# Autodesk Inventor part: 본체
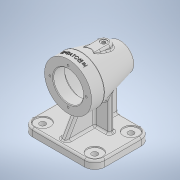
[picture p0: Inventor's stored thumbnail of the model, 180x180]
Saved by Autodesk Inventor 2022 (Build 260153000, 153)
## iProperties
Created: 2024-12
Part Number: 본체
Material: 일반
Document SubType Name: Modeling
Designer: PC-12
Density: 1 g/cm^3
Appearance: 기본값
Author: PC-12
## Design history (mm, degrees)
sketch "스케치1"
  geometry: L1 (0, -42)-(37, -42); L2 (37, -42)-(37, -22); L3 (37, -22)-(0, -22); L4 (0, -22)-(0, -42); L5 (37, -22)-(21, 42); L6 (21, 42)-(0, 42); L7 (0, 42)-(0, -22); L8 (-7.4, 0)-(44.4, 0) reference; 1 further point
  constraints: 14 end point, 2 horizontal, 2 parallel, 1 perpendicular, 1 point on line, 1 vertical, 1 other
  dimensions: "d0" = 74 diameter of L2 L4; "d1" = 84 distance between parallel lines of L6 L1; "d2" = 20 distance of L1.end L2.end; "d3" = 42 diameter of L5.end L7
revolve "회전1" sketch "스케치1" stored, may be unused: angle "d4" = 90 deg
node "작업 평면1"
sketch "스케치2"
  geometry: L1 (-57, 32)-(57, 32); L2 (57, 32)-(57, -57); L3 (57, -57)-(-57, -57); L4 (-57, -57)-(-57, 32); L5 (-21, 42)-(21, 42) reference; L6 (-37, -42)-(37, -42) reference; L7 (0, -90.26)-(0, 64.043) reference; 1 further point
  constraints: 8 end point, 2 parallel, 1 horizontal, 1 perpendicular, 1 other
  dimensions: "d6" = 89 distance of L3.end L1.start; "d7" = 114 distance of L2.end L3.end; "d8" = 15 distance between parallel lines of L6 L3
extrude "돌출1" join sketch "스케치2" distance "d9" = 12; taper "d10" = 0 deg
sketch "스케치3"
  geometry: L1 (28, -3)-(-28, -3); L2 (-28, -3)-(-28, 5); L3 (-28, 5)-(28, 5); L4 (28, 5)-(28, -3); L5 (28, -3)-(-28, 5); L6 (-28, -3)-(28, 5); L7 (-57, -32)-(57, -32) reference; L8 (0, 76.8)-(0, -61.8) reference; L9 (5, -32)-(-5, -32); L10 (-5, -32)-(-5, -3); L11 (-5, -3)-(5, -3); L12 (5, -3)-(5, -32); 5 further points
  constraints: 20 end point, 4 parallel, 3 midpoint, 3 point on line, 2 horizontal, 2 perpendicular, 1 other
  dimensions: "d11" = 29 distance between parallel lines of L7 L1; "d12" = 8 distance of L1.end L2.end; "d13" = 56 distance of L2.end L3.end; "d14" = 10 distance between parallel lines of L12 L10
extrude "돌출2" join sketch "스케치3" stored distance "d15" = 12; taper "d16" = 0 deg
sketch "스케치4"
  geometry: L1 (-70, 32)-(-70, -57) reference; L2 (-70, -50)-(0, -9.585); L3 (0, -76.8)-(0, 61.8) reference; L4 (-82, -57)-(-70, -57) reference; 1 further point
  constraints: 2 end point, 2 point on line
  dimensions: "d17" = 7 distance from line of L2.start L4; "d18" = 60 deg angle of L2 L1
feature "리브1" sketch "스케치4" dims "d19" = 1, "d20" = 10, "d21" = 0, "d22" = 0, "d23" = 1, "d24" = 1
sketch "스케치5" dims "d25" = 20
  geometry: L1 (-10, 14)-(10, 14); L2 (10, 14)-(10, -42); L3 (10, -42)-(-10, -42); L4 (-10, -42)-(-10, 14); L5 (-37, -42)-(37, -42) reference; L6 (0, 0)-(0, 14); 1 further point
  constraints: 10 end point, 3 vertical, 2 parallel, 1 collinear, 1 horizontal, 1 perpendicular, 3 other
  dimensions: "d26" = 56 distance between parallel lines of L1 L5
extrude "돌출3" join sketch "스케치5" distance "d27" = 33; taper "d28" = 0 deg
fillet "모깎기1" dims "d29" = 16
sketch "스케치6"
  geometry: A1 r 16 centre (41, 41) between (57, 41) and (41, 57) reference; A2 r 16 centre (41, -16) between (41, -32) and (57, -16) reference; A3 r 16 centre (-41, -16) between (-57, -16) and (-41, -32) reference; A4 r 16 centre (-41, 41) between (-41, 57) and (-57, 41) reference; 5 further points
  constraints: 4 coincident
hole "구멍1" sketch "스케치6" at (41, 41), (41, -16), (-41, -16), (-41, 41) diameter "d30" = 9; stored, may be unused: countersink angle "d34" = 90 deg, drill point angle "d36" = 118 deg; dims "d31" = 8, "d32" = 24, "d33" = 2, "d35" = 10
sketch "스케치7"
  geometry: L1 (-37, -42)-(37, -42) reference; L2 (23.5, -42)-(0, -42); L3 (0, -42)-(0, -24); L4 (0, -24)-(23.5, -24); L5 (23.5, -24)-(23.5, -42); L6 (-21, 42)-(21, 42) reference; L7 (0, -24)-(0, 21); L8 (23.5, -24)-(32.346, -24); L9 (32.346, -24)-(21.096, 21); L10 (21, 42)-(37, -22) reference; L11 (0, 21)-(17.5, 21); L12 (17.5, 21)-(17.5, 31); L13 (17.5, 31)-(0, 31); L14 (0, 31)-(0, 21); L15 (21.096, 21)-(17.5, 21); L16 (0, 31)-(15.5, 31); L17 (15.5, 31)-(15.5, 34); L18 (15.5, 34)-(0, 34); L19 (0, 34)-(0, 31); 2 further points
  constraints: 32 end point, 7 parallel, 5 horizontal, 3 perpendicular, 2 point on line, 1 vertical
  dimensions: "d37" = 18 distance of L4.end L2.start; "d38" = 47 diameter of L5 L3; "d41" = 5 distance between parallel lines of L10 L9; "d42" = 45 distance between parallel lines of L11 L4; "d43" = 35 diameter of L12 L14; "d44" = 31 diameter of L17 L19; "d45" = 10 distance of L11.end L12.end; "d46" = 3 distance of L16.end L17.end
revolve "회전2" sketch "스케치7" stored, may be unused: angle "d47" = 90 deg
sketch "스케치8"
  geometry: A1 r 10 centre (0, -14) between (-10, -14) and (10, -14) reference; 2 further points
  constraints: 1 coincident
hole "구멍2" sketch "스케치8" at (0, -14) diameter "d48" = 5.1881; stored, may be unused: countersink angle "d52" = 90 deg, drill point angle "d54" = 0 deg; dims "d49" = 100, "d50" = 10, "d51" = 1, "d53" = 8
sketch "스케치9"
  geometry: L1 (0, 0)-(0, 28.5)
  constraints: 2 end point, 1 vertical
  dimensions: "d55" = 28.5 distance of L1.start L1.end
hole "구멍3" sketch "스케치9" at (0, 28.5) diameter "d56" = 3.242; stored, may be unused: countersink angle "d60" = 90 deg, drill point angle "d62" = 118 deg; dims "d57" = 8, "d58" = 10, "d59" = 1, "d61" = 10
node "작업 평면2"
sketch "스케치10"
  geometry: L1 (-21.075, 2.002)-(21.075, 2.002); L2 (21.075, 2.002)-(21.075, -4.002); L3 (21.075, -4.002)-(-21.075, -4.002); L4 (-21.075, -4.002)-(-21.075, 2.002); L5 (-21.075, -1)-(21.075, -1); L6 (0, 2.002)-(0, -4.002); L7 (-37, -10)-(37, -10) reference; 1 further point
  constraints: 4 end point, 4 midpoint, 1 point on line, 2 other
  dimensions: "d66" = 9 distance between parallel lines of L5 L7
feature "엠보싱1" sketch "스케치10" dims "d0" = 74, "d1" = 84, "d2" = 20, "d3" = 42, "d67" = 0.5, "d68" = 0
fillet "모깎기2" dims "d69" = 0.3
fillet "모깎기3" dims "d70" = 5
fillet "모깎기4" dims "d71" = 3
chamfer "모따기1" distance "d72" = 1; stored, may be unused: second distance "d73" = 2, angle "d74" = 45 deg
fillet "모깎기5" dims "d75" = 3
fillet "모깎기6" dims "d76" = 3
fillet "모깎기7" dims "d77" = 3
fillet "모깎기8" dims "d78" = 3
fillet "모깎기9" dims "d79" = 3
fillet "모깎기10" dims "d80" = 3
fillet "모깎기11" dims "d81" = 3
node "솔리드1"
pattern_circular "원형 패턴1" dims angle "d64" = 360 deg
feature "A9D066F2-1C7D-4E18-AEED-F7BC21143FA4" dims "d30" = 9, "d31" = 8, "d32" = 24, "d33" = 2, "d34" = 90 deg, "d35" = 10, "d36" = 118 deg
other parameters: "d5" = -82
